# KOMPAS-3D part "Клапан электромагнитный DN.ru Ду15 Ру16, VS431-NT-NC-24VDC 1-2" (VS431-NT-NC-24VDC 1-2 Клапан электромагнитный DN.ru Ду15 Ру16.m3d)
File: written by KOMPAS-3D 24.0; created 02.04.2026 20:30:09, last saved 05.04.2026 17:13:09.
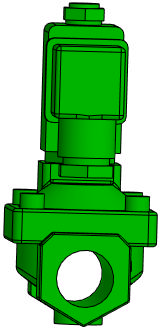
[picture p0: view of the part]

Document properties: Автор: artio; Полное имя файла: C:\Users\artio\OneDrive\Рабочий стол\Клапан электромагнитный DN.ru\VS431\VS431-NT-NC\VS431-NT-NC-24VDC\Ду15\VS431-NT-NC-24VDC 1-2 Клапан электромагнитный DN.ru Ду15 Ру16.m3d

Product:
- Body: Тело 1  | qty 1
    Масса: 1.030062
- Part/product: Клапан электромагнитный DN.ru Ду15 Ру16  | designation VS431-NT-NC-24VDC 1-2
    Масса: 0.732
    Раздел спецификации: Прочие изделия
    Примечание: D130-04747
    additional columns: ef56311e-7521-43dc-8291-0e6108b3d81d; VS400-ET-NC-220VAC 1-2; artio; c; Шероховатость не задана; Да

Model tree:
1. Операция без истории:1

Expressions: VS431-NT-NC-24VDC 1-2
